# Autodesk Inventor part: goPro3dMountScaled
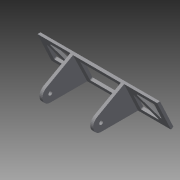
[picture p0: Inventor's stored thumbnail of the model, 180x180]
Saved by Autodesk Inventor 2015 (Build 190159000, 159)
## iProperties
Created: 2015-02
Part Number: goPro3dMountScaled
Material: Generic
Document SubType Name: Modeling
Designer: sungeun
Density: 1 g/cm^3
Appearance: Default
Author: sungeun
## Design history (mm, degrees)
feature "cameraMount"
sketch "Sketch6"
  geometry: L1 (0, 0)-(0, 26) reference; L2 (30, 0)-(30, 3) reference; L3 (14.986, 29.899)-(30, 3) reference; L4 (14.253, 30.991)-(14.986, 29.899) reference; L5 (13.351, 31.947)-(14.253, 30.991) reference; L6 (12.304, 32.744)-(13.351, 31.947) reference; L7 (11.142, 33.357)-(12.304, 32.744) reference; L8 (9.894, 33.773)-(11.142, 33.357) reference; L9 (8.596, 33.978)-(9.894, 33.773) reference; L10 (7.281, 33.968)-(8.596, 33.978) reference; L11 (5.986, 33.742)-(7.281, 33.968) reference; L12 (4.745, 33.308)-(5.986, 33.742) reference; L13 (3.592, 32.676)-(4.745, 33.308) reference; L14 (2.558, 31.864)-(3.592, 32.676) reference; L15 (1.671, 30.893)-(2.558, 31.864) reference; L16 (0.955, 29.791)-(1.671, 30.893) reference; L17 (0.429, 28.585)-(0.955, 29.791) reference; L18 (0.108, 27.31)-(0.429, 28.585) reference; L19 (0, 26)-(0.108, 27.31) reference; L20 (30, 0)-(1.149, -13.453); L21 (0, -10.989)-(0, 0); L22 (0, 0)-(30, 0); L23 (1.149, -13.453)-(0, -10.989); L24 (30, 3)-(0, -10.989); C1 r 0.996 at (8, 26); C2 r 2 at (8, 26); 2 further points
  constraints: 11 end point, 2 centre point, 2 coincident, 1 horizontal, 1 parallel, 1 vertical
  dimensions: "d3" = 115 deg angle of L2 L20; "d6" = 26 distance from line of L22 C1.centre; "d16" = 4 diameter of C2; "d21" = 90 deg angle of L20 L23
extrude "Extrusion2" new body sketch "Sketch6" distance "d7" = 54; taper "d8" = 0 deg
sketch "Sketch7"
  geometry: L1 (0, 33.425)-(54, 33.425) reference; L2 (54, 33.425)-(54, 30.806) reference; L3 (54, 30.806)-(54, 0) reference; L4 (0, 30.806)-(0, 0) reference; L5 (0, 33.425)-(0, 30.806) reference; L6 (51, -14.575)-(3, -14.575); L7 (3, -8.066)-(3, 30.425); L8 (3, 30.425)-(51, 30.425); L9 (51, 30.425)-(51, -8.066); L10 (51, -8.066)-(51, -14.575); L11 (0, -7.978)-(54, -7.978) reference; L12 (3, -14.575)-(3, -8.066); 1 further point
  constraints: 12 end point, 3 parallel, 2 perpendicular, 1 horizontal
  dimensions: "d9" = 3 distance between parallel lines of L3 L9; "d10" = 3 distance between parallel lines of L4 L7; "d11" = 3 distance between parallel lines of L1 L8; "d19" = 45 distance between parallel lines of L8 L6
extrude "Extrusion4" cut sketch "Sketch6" distance "d14" = 54; taper "d15" = 0 deg
extrude "Extrusion5" cut sketch "Sketch6" stored distance "d17" = 54; taper "d18" = 0 deg
extrude "Extrusion6" join sketch "Sketch6" distance "d22" = 33; taper "d23" = 0 deg
extrude "Extrusion7" join sketch "Sketch6" distance "d24" = 87; taper "d25" = 0 deg
sketch "Sketch8"
  geometry: L1 (8.515, -5)-(28, -5); L2 (28, -5)-(28, -24.545); L3 (28, -24.545)-(8.515, -5); L4 (33, -33.101)-(33, 0) reference; L5 (33, 0)-(0, 0) reference; L6 (0, -33.101)-(0, 0) reference; L7 (33, -33.101)-(0, -33.101) reference; L8 (0, 0)-(33, -33.101); L9 (4.914, -28.015)-(24.459, -28.075); L10 (4.974, -8.53)-(4.914, -28.015); L11 (24.459, -28.075)-(4.974, -8.53); L12 (82.005, -0.028)-(79.613, -32.924) reference; L13 (37.995, -0.028)-(82.005, -0.028) reference; L14 (40.387, -32.924)-(37.995, -0.028) reference; L15 (79.613, -32.924)-(40.387, -32.924) reference; 1 further point
  constraints: 14 end point, 3 symmetric about line, 1 horizontal, 1 parallel, 1 perpendicular
  dimensions: "d26" = 5 distance between parallel lines of L1 L5; "d27" = 5 distance between parallel lines of L4 L2; "d28" = 2.5 distance between parallel lines of L8 L3
extrude "Extrusion8" cut sketch "Sketch8" stored distance "d29" = 87; taper "d30" = 0 deg
fillet "Fillet2" dims "d31" = 1
pattern_linear "Rectangular Pattern1" dims "d34" = 87
sketch "Sketch9"
  geometry: 1 further point
sketch "Sketch11"
  geometry: L1 (3, -36.989)-(51, -36.989); L2 (51, -36.989)-(51, 9.794); L3 (51, 9.794)-(3, 9.794); L4 (3, 9.794)-(3, -36.989); L5 (54, 0)-(54, -36.989) reference; L6 (0, 0)-(0, -36.989) reference; L7 (0, -36.989)-(54, -36.989) reference; 1 further point
  constraints: 8 end point, 2 parallel, 1 horizontal, 1 perpendicular
  dimensions: "d35" = 3 distance between parallel lines of L5 L2; "d36" = 3 distance between parallel lines of L6 L4; "d37" = 0 distance between parallel lines of L7 L1
loft "Loft1" sketch "Sketch11" dims "d38" = 0, "d39" = 90 deg, "d40" = 0, "d41" = 90 deg
sketch "Sketch12"
  geometry: L1 (43, -5)-(5, -5); L2 (5, -5)-(5, -28.076); L3 (5, -28.076)-(43, -28.076); L4 (43, -28.076)-(43, -5); L5 (0, -33.076)-(48, -33.076) reference; L6 (0, -33.076)-(0, -17.06) reference; L7 (0, 0)-(48, 0) reference; L8 (48, -17.06)-(48, -33.076) reference; 1 further point
  constraints: 8 end point, 2 parallel, 1 horizontal, 1 perpendicular
  dimensions: "d42" = 5 distance between parallel lines of L5 L3; "d43" = 5 distance between parallel lines of L6 L2; "d44" = 5 distance between parallel lines of L7 L1; "d45" = 5 distance between parallel lines of L8 L4
extrude "Extrusion9" cut sketch "Sketch12" stored distance "d46" = 87; taper "d47" = 0 deg
fillet "Fillet3" dims "d48" = 1
sketch "Sketch13"
  geometry: L1 (0, 0)-(60, 0); L2 (120, 0)-(0, 0) reference; 1 further point
  constraints: 2 end point, 1 midpoint
body "Solid2"
node "Projected Loop4"
